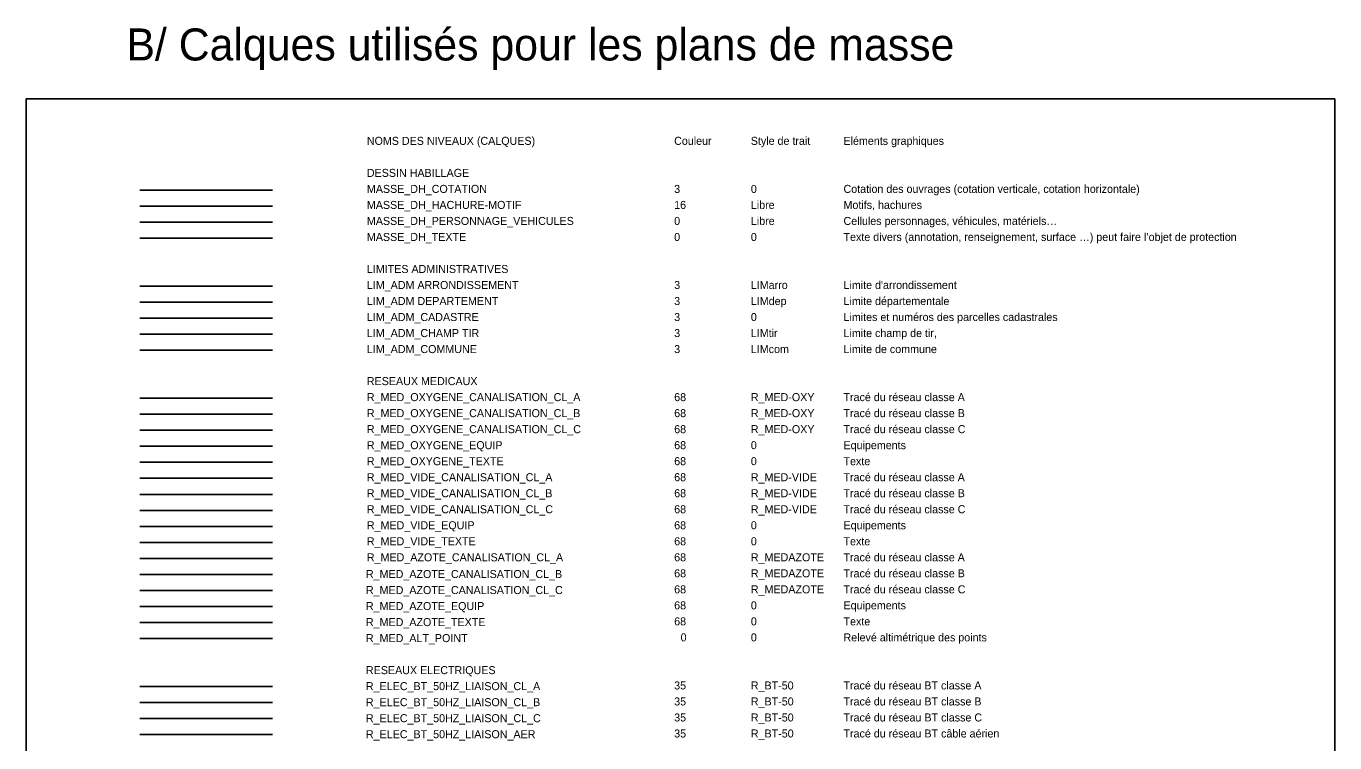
# Model space of a CAD drawing. Extents: x -60 to 214, y -380 to -21.
# Drawn here: x 33.1 to 114.8, y -65.9 to -21.2 of the extents above; entities that cross this region are included whole.
import ezdxf

# ---------------------------------------------------------------- set-up
doc = ezdxf.new("R2010")
doc.units = 0
for name, color, linetype in [('Default', 7, 'Continuous'), ('DH_TEXTE', 7, 'Continuous'), ('LIM_ADM ARRONDISSEMENT', 7, 'Continuous'), ('LIM_ADM DEPARTEMENT', 7, 'Continuous'), ('LIM_ADM_CADASTRE', 7, 'Continuous'), ('LIM_ADM_CHAMP TIR', 7, 'Continuous'), ('LIM_ADM_COMMUNE', 7, 'Continuous'), ('MASSE_DH_COTATION', 7, 'Continuous'), ('MASSE_DH_HACHURE-MOTIF', 7, 'Continuous'), ('MASSE_DH_PERSONNAGE_VEHICULES', 7, 'Continuous'), ('MASSE_DH_TEXTE', 7, 'Continuous'), ('R_ELEC_BT_50HZ_LIAISON_CL_A', 7, 'Continuous'), ('R_ELEC_BT_50HZ_LIAISON_CL_B', 7, 'Continuous'), ('R_ELEC_BT_50HZ_LIAISON_CL_C', 7, 'Continuous'), ('R_MED_ALT_POINT', 7, 'Continuous'), ('R_MED_AZOTE_CANALISATION_CL_A', 7, 'Continuous'), ('R_MED_AZOTE_CANALISATION_CL_B', 7, 'Continuous'), ('R_MED_AZOTE_CANALISATION_CL_C', 7, 'Continuous'), ('R_MED_AZOTE_EQUIP', 7, 'Continuous'), ('R_MED_AZOTE_TEXTE', 7, 'Continuous'), ('R_MED_OXYGENE_CANALISATION_CL_A', 7, 'Continuous'), ('R_MED_OXYGENE_CANALISATION_CL_B', 7, 'Continuous'), ('R_MED_OXYGENE_CANALISATION_CL_C', 7, 'Continuous'), ('R_MED_OXYGENE_EQUIP', 7, 'Continuous'), ('R_MED_OXYGENE_TEXTE', 7, 'Continuous'), ('R_MED_VIDE_CANALISATION_CL_A', 7, 'Continuous'), ('R_MED_VIDE_CANALISATION_CL_B', 7, 'Continuous'), ('R_MED_VIDE_CANALISATION_CL_C', 7, 'Continuous'), ('R_MED_VIDE_EQUIP', 7, 'Continuous'), ('R_MED_VIDE_TEXTE', 7, 'Continuous')]:
    doc.layers.add(name, color=color, linetype=linetype)

msp = doc.modelspace()

# ---------------------------------------------------------------- linework, layer by layer
at = {"layer": 'Default'}
msp.add_line((40.178, -65.429), (48.457, -65.429), dxfattribs=at)
msp.add_lwpolyline([(114.838, -25.727), (33.073, -25.727), (33.073, -380.216), (114.838, -380.216)], close=True, dxfattribs=at)
at = {"layer": 'LIM_ADM ARRONDISSEMENT'}
msp.add_line((48.457, -37.429), (40.178, -37.429), dxfattribs=at)
at = {"layer": 'LIM_ADM DEPARTEMENT'}
msp.add_line((40.178, -38.429), (48.457, -38.429), dxfattribs=at)
at = {"layer": 'LIM_ADM_CADASTRE'}
msp.add_line((40.178, -39.429), (48.457, -39.429), dxfattribs=at)
at = {"layer": 'LIM_ADM_CHAMP TIR'}
msp.add_line((40.178, -40.429), (48.457, -40.429), dxfattribs=at)
at = {"layer": 'LIM_ADM_COMMUNE'}
msp.add_line((40.178, -41.429), (48.457, -41.429), dxfattribs=at)
at = {"layer": 'MASSE_DH_COTATION'}
msp.add_line((40.178, -31.429), (48.457, -31.429), dxfattribs=at)
at = {"layer": 'MASSE_DH_HACHURE-MOTIF'}
msp.add_line((40.178, -32.429), (48.457, -32.429), dxfattribs=at)
at = {"layer": 'MASSE_DH_PERSONNAGE_VEHICULES'}
msp.add_line((40.178, -33.429), (48.457, -33.429), dxfattribs=at)
at = {"layer": 'MASSE_DH_TEXTE'}
msp.add_line((40.178, -34.429), (48.457, -34.429), dxfattribs=at)
at = {"layer": 'R_ELEC_BT_50HZ_LIAISON_CL_A'}
msp.add_line((40.178, -62.429), (48.457, -62.429), dxfattribs=at)
at = {"layer": 'R_ELEC_BT_50HZ_LIAISON_CL_B'}
msp.add_line((40.178, -63.429), (48.457, -63.429), dxfattribs=at)
at = {"layer": 'R_ELEC_BT_50HZ_LIAISON_CL_C'}
msp.add_line((40.178, -64.429), (48.457, -64.429), dxfattribs=at)
at = {"layer": 'R_MED_ALT_POINT'}
msp.add_line((40.178, -59.429), (48.457, -59.429), dxfattribs=at)
at = {"layer": 'R_MED_AZOTE_CANALISATION_CL_A'}
msp.add_line((40.178, -54.429), (48.457, -54.429), dxfattribs=at)
at = {"layer": 'R_MED_AZOTE_CANALISATION_CL_B'}
msp.add_line((40.178, -55.429), (48.457, -55.429), dxfattribs=at)
at = {"layer": 'R_MED_AZOTE_CANALISATION_CL_C'}
msp.add_line((40.178, -56.429), (48.457, -56.429), dxfattribs=at)
at = {"layer": 'R_MED_AZOTE_EQUIP'}
msp.add_line((40.178, -57.429), (48.457, -57.429), dxfattribs=at)
at = {"layer": 'R_MED_AZOTE_TEXTE'}
msp.add_line((40.178, -58.429), (48.457, -58.429), dxfattribs=at)
at = {"layer": 'R_MED_OXYGENE_CANALISATION_CL_A'}
msp.add_line((40.178, -44.429), (48.457, -44.429), dxfattribs=at)
at = {"layer": 'R_MED_OXYGENE_CANALISATION_CL_B'}
msp.add_line((40.178, -45.429), (48.457, -45.429), dxfattribs=at)
at = {"layer": 'R_MED_OXYGENE_CANALISATION_CL_C'}
msp.add_line((40.178, -46.429), (48.457, -46.429), dxfattribs=at)
at = {"layer": 'R_MED_OXYGENE_EQUIP'}
msp.add_line((40.178, -47.429), (48.457, -47.429), dxfattribs=at)
at = {"layer": 'R_MED_OXYGENE_TEXTE'}
msp.add_line((40.178, -48.429), (48.457, -48.429), dxfattribs=at)
at = {"layer": 'R_MED_VIDE_CANALISATION_CL_A'}
msp.add_line((40.178, -49.429), (48.457, -49.429), dxfattribs=at)
at = {"layer": 'R_MED_VIDE_CANALISATION_CL_B'}
msp.add_line((40.178, -50.429), (48.457, -50.429), dxfattribs=at)
at = {"layer": 'R_MED_VIDE_CANALISATION_CL_C'}
msp.add_line((40.178, -51.429), (48.457, -51.429), dxfattribs=at)
at = {"layer": 'R_MED_VIDE_EQUIP'}
msp.add_line((40.178, -52.429), (48.457, -52.429), dxfattribs=at)
at = {"layer": 'R_MED_VIDE_TEXTE'}
msp.add_line((40.178, -53.429), (48.457, -53.429), dxfattribs=at)

# ---------------------------------------------------------------- texts
at = {"layer": 'Default'}
msp.add_text('B/ Calques utilisés pour les plans de masse', height=2, dxfattribs=at).set_placement((39.335, -23.342))
at = {"layer": 'DH_TEXTE'}
for s, p in [('NOMS DES NIVEAUX (CALQUES) ', (54.36, -28.61)), ('Couleur ', (73.559, -28.61)), ('Style de trait ', (78.348, -28.61)), ('Eléments graphiques ', (84.138, -28.61)), ('DESSIN HABILLAGE ', (54.36, -30.61)), ('LIMITES ADMINISTRATIVES', (54.36, -36.61)), ('RESEAUX MEDICAUX ', (54.36, -43.61)), ('0', (73.964, -59.611)), ('RESEAUX ELECTRIQUES ', (54.301, -61.655)), ('R_ELEC_BT_50HZ_LIAISON_AER ', (54.301, -65.655)), ('35 ', (73.561, -65.61)), ('R_BT-50 ', (78.351, -65.61)), ('Tracé du réseau BT câble aérien ', (84.14, -65.61))]:
    msp.add_text(s, height=0.5, dxfattribs=at).set_placement(p)
at = {"layer": 'LIM_ADM ARRONDISSEMENT'}
for s, p in [('LIM_ADM ARRONDISSEMENT  ', (54.36, -37.61)), ('3 ', (73.561, -37.61)), ('LIMarro  ', (78.351, -37.61)), ("Limite d'arrondissement ", (84.14, -37.61))]:
    msp.add_text(s, height=0.5, dxfattribs=at).set_placement(p)
at = {"layer": 'LIM_ADM DEPARTEMENT'}
for s, p in [('LIM_ADM DEPARTEMENT  ', (54.36, -38.61)), ('3 ', (73.561, -38.61)), ('LIMdep  ', (78.351, -38.61)), ('Limite départementale ', (84.14, -38.61))]:
    msp.add_text(s, height=0.5, dxfattribs=at).set_placement(p)
at = {"layer": 'LIM_ADM_CADASTRE'}
for s, p in [('LIM_ADM_CADASTRE ', (54.36, -39.61)), ('3 ', (73.561, -39.61)), ('0 ', (78.351, -39.61)), ('Limites et numéros des parcelles cadastrales ', (84.14, -39.61))]:
    msp.add_text(s, height=0.5, dxfattribs=at).set_placement(p)
at = {"layer": 'LIM_ADM_CHAMP TIR'}
for s, p in [('LIM_ADM_CHAMP TIR  ', (54.36, -40.61)), ('3 ', (73.561, -40.61)), ('LIMtir  ', (78.351, -40.61)), ('Limite champ de tir,  ', (84.14, -40.61))]:
    msp.add_text(s, height=0.5, dxfattribs=at).set_placement(p)
at = {"layer": 'LIM_ADM_COMMUNE'}
for s, p in [('LIM_ADM_COMMUNE ', (54.36, -41.61)), ('3 ', (73.561, -41.61)), ('LIMcom  ', (78.351, -41.61)), ('Limite de commune ', (84.14, -41.61))]:
    msp.add_text(s, height=0.5, dxfattribs=at).set_placement(p)
at = {"layer": 'MASSE_DH_COTATION'}
for s, p in [('MASSE_DH_COTATION  ', (54.36, -31.61)), ('3 ', (73.561, -31.61)), ('0 ', (78.351, -31.61)), ('Cotation des ouvrages (cotation verticale, cotation horizontale) ', (84.14, -31.61))]:
    msp.add_text(s, height=0.5, dxfattribs=at).set_placement(p)
at = {"layer": 'MASSE_DH_HACHURE-MOTIF'}
for s, p in [('MASSE_DH_HACHURE-MOTIF ', (54.36, -32.61)), ('16 ', (73.561, -32.61)), ('Libre ', (78.351, -32.61)), ('Motifs, hachures ', (84.14, -32.61))]:
    msp.add_text(s, height=0.5, dxfattribs=at).set_placement(p)
at = {"layer": 'MASSE_DH_PERSONNAGE_VEHICULES'}
for s, p in [('MASSE_DH_PERSONNAGE_VEHICULES ', (54.36, -33.61)), ('0 ', (73.561, -33.61)), ('Libre ', (78.351, -33.61)), ('Cellules personnages, véhicules, matériels…', (84.14, -33.61))]:
    msp.add_text(s, height=0.5, dxfattribs=at).set_placement(p)
at = {"layer": 'MASSE_DH_TEXTE'}
for s, p in [('MASSE_DH_TEXTE  ', (54.36, -34.61)), ('0 ', (73.561, -34.61)), ('0 ', (78.351, -34.61)), ('Texte divers (annotation, renseignement, surface …) peut faire l’objet de protection ', (84.14, -34.61))]:
    msp.add_text(s, height=0.5, dxfattribs=at).set_placement(p)
at = {"layer": 'R_ELEC_BT_50HZ_LIAISON_CL_A'}
for s, p in [('35 ', (73.559, -62.61)), ('R_BT-50 ', (78.348, -62.61)), ('Tracé du réseau BT classe A ', (84.138, -62.61)), ('R_ELEC_BT_50HZ_LIAISON_CL_A ', (54.301, -62.655))]:
    msp.add_text(s, height=0.5, dxfattribs=at).set_placement(p)
at = {"layer": 'R_ELEC_BT_50HZ_LIAISON_CL_B'}
for s, p in [('R_ELEC_BT_50HZ_LIAISON_CL_B ', (54.301, -63.655)), ('35 ', (73.561, -63.61)), ('R_BT-50 ', (78.351, -63.61)), ('Tracé du réseau BT classe B ', (84.14, -63.61))]:
    msp.add_text(s, height=0.5, dxfattribs=at).set_placement(p)
at = {"layer": 'R_ELEC_BT_50HZ_LIAISON_CL_C'}
for s, p in [('R_ELEC_BT_50HZ_LIAISON_CL_C ', (54.301, -64.655)), ('35 ', (73.561, -64.61)), ('R_BT-50 ', (78.351, -64.61)), ('Tracé du réseau BT classe C ', (84.14, -64.61))]:
    msp.add_text(s, height=0.5, dxfattribs=at).set_placement(p)
at = {"layer": 'R_MED_ALT_POINT'}
for s, p in [('R_MED_ALT_POINT  ', (54.301, -59.655)), ('0 ', (78.351, -59.61)), ('Relevé altimétrique des points ', (84.14, -59.61))]:
    msp.add_text(s, height=0.5, dxfattribs=at).set_placement(p)
at = {"layer": 'R_MED_AZOTE_CANALISATION_CL_A'}
for s, p in [('R_MED_AZOTE_CANALISATION_CL_A ', (54.36, -54.61)), ('68 ', (73.561, -54.61)), ('R_MEDAZOTE ', (78.351, -54.61)), ('Tracé du réseau classe A ', (84.14, -54.61))]:
    msp.add_text(s, height=0.5, dxfattribs=at).set_placement(p)
at = {"layer": 'R_MED_AZOTE_CANALISATION_CL_B'}
for s, p in [('R_MED_AZOTE_CANALISATION_CL_B ', (54.301, -55.655)), ('68 ', (73.561, -55.61)), ('R_MEDAZOTE ', (78.351, -55.61)), ('Tracé du réseau classe B ', (84.14, -55.61))]:
    msp.add_text(s, height=0.5, dxfattribs=at).set_placement(p)
at = {"layer": 'R_MED_AZOTE_CANALISATION_CL_C'}
for s, p in [('R_MED_AZOTE_CANALISATION_CL_C ', (54.301, -56.655)), ('68 ', (73.561, -56.61)), ('R_MEDAZOTE ', (78.351, -56.61)), ('Tracé du réseau classe C ', (84.14, -56.61))]:
    msp.add_text(s, height=0.5, dxfattribs=at).set_placement(p)
at = {"layer": 'R_MED_AZOTE_EQUIP'}
for s, p in [('R_MED_AZOTE_EQUIP ', (54.301, -57.655)), ('68 ', (73.561, -57.61)), ('0 ', (78.351, -57.61)), ('Equipements ', (84.14, -57.61))]:
    msp.add_text(s, height=0.5, dxfattribs=at).set_placement(p)
at = {"layer": 'R_MED_AZOTE_TEXTE'}
for s, p in [('R_MED_AZOTE_TEXTE ', (54.301, -58.655)), ('68', (73.561, -58.61)), ('0 ', (78.351, -58.61)), ('Texte ', (84.14, -58.61))]:
    msp.add_text(s, height=0.5, dxfattribs=at).set_placement(p)
at = {"layer": 'R_MED_OXYGENE_CANALISATION_CL_A'}
for s, p in [('R_MED_OXYGENE_CANALISATION_CL_A ', (54.36, -44.61)), ('68 ', (73.561, -44.61)), ('R_MED-OXY ', (78.351, -44.61)), ('Tracé du réseau classe A ', (84.14, -44.61))]:
    msp.add_text(s, height=0.5, dxfattribs=at).set_placement(p)
at = {"layer": 'R_MED_OXYGENE_CANALISATION_CL_B'}
for s, p in [('R_MED_OXYGENE_CANALISATION_CL_B ', (54.36, -45.61)), ('68 ', (73.561, -45.61)), ('R_MED-OXY ', (78.351, -45.61)), ('Tracé du réseau classe B ', (84.14, -45.61))]:
    msp.add_text(s, height=0.5, dxfattribs=at).set_placement(p)
at = {"layer": 'R_MED_OXYGENE_CANALISATION_CL_C'}
for s, p in [('R_MED_OXYGENE_CANALISATION_CL_C ', (54.36, -46.61)), ('68 ', (73.561, -46.61)), ('R_MED-OXY ', (78.351, -46.61)), ('Tracé du réseau classe C ', (84.14, -46.61))]:
    msp.add_text(s, height=0.5, dxfattribs=at).set_placement(p)
at = {"layer": 'R_MED_OXYGENE_EQUIP'}
for s, p in [('R_MED_OXYGENE_EQUIP ', (54.36, -47.61)), ('68 ', (73.561, -47.61)), ('0 ', (78.351, -47.61)), ('Equipements ', (84.14, -47.61))]:
    msp.add_text(s, height=0.5, dxfattribs=at).set_placement(p)
at = {"layer": 'R_MED_OXYGENE_TEXTE'}
for s, p in [('R_MED_OXYGENE_TEXTE ', (54.36, -48.61)), ('68 ', (73.561, -48.61)), ('0 ', (78.351, -48.61)), ('Texte ', (84.14, -48.61))]:
    msp.add_text(s, height=0.5, dxfattribs=at).set_placement(p)
at = {"layer": 'R_MED_VIDE_CANALISATION_CL_A'}
for s, p in [('R_MED_VIDE_CANALISATION_CL_A ', (54.36, -49.61)), ('68 ', (73.561, -49.61)), ('R_MED-VIDE ', (78.351, -49.61)), ('Tracé du réseau classe A ', (84.14, -49.61))]:
    msp.add_text(s, height=0.5, dxfattribs=at).set_placement(p)
at = {"layer": 'R_MED_VIDE_CANALISATION_CL_B'}
for s, p in [('R_MED_VIDE_CANALISATION_CL_B ', (54.36, -50.61)), ('68 ', (73.561, -50.61)), ('R_MED-VIDE ', (78.351, -50.61)), ('Tracé du réseau classe B ', (84.14, -50.61))]:
    msp.add_text(s, height=0.5, dxfattribs=at).set_placement(p)
at = {"layer": 'R_MED_VIDE_CANALISATION_CL_C'}
for s, p in [('R_MED_VIDE_CANALISATION_CL_C ', (54.36, -51.61)), ('68 ', (73.561, -51.61)), ('R_MED-VIDE ', (78.351, -51.61)), ('Tracé du réseau classe C ', (84.14, -51.61))]:
    msp.add_text(s, height=0.5, dxfattribs=at).set_placement(p)
at = {"layer": 'R_MED_VIDE_EQUIP'}
for s, p in [('R_MED_VIDE_EQUIP ', (54.36, -52.61)), ('68 ', (73.561, -52.61)), ('0 ', (78.351, -52.61)), ('Equipements ', (84.14, -52.61))]:
    msp.add_text(s, height=0.5, dxfattribs=at).set_placement(p)
at = {"layer": 'R_MED_VIDE_TEXTE'}
for s, p in [('R_MED_VIDE_TEXTE ', (54.36, -53.61)), ('68 ', (73.561, -53.61)), ('0 ', (78.351, -53.61)), ('Texte ', (84.14, -53.61))]:
    msp.add_text(s, height=0.5, dxfattribs=at).set_placement(p)

doc.saveas('drawing.dxf')
